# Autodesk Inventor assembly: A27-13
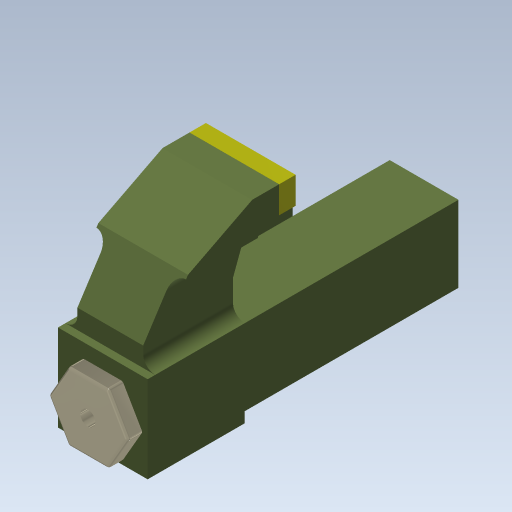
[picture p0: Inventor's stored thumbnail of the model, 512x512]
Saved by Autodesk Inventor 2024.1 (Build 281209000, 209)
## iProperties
Created: 2008-07
Part Number: A27-13
Document SubType Name: Assembly
Designer: y-shimohigashi
Stock Number: A24-13
Author: y-shimohigashi
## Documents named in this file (5)
- C:\Users\h-sato\Desktop\ブログ用モデル\Inventor\図面の作成\A27-13.iam
- C:\Users\h-sato\Desktop\R2024\Inventor2024基礎コース\練習問題\練習問題-27\P27-4締付板.ipt
- C:\Users\h-sato\Desktop\R2024\Inventor2024基礎コース\練習問題\練習問題-27\P27-6締付ネジ押え板.ipt
- C:\Users\h-sato\Desktop\R2024\Inventor2024基礎コース\練習問題\練習問題-27\P27-3締付金具.ipt
- C:\Users\h-sato\Desktop\R2024\Inventor2024基礎コース\練習問題\練習問題-27\P27-11ボルト.ipt
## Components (5 placed, 4 different names)
1. P27-4締付板:1 — 挿入:3, 挿入:4
2. P27-6締付ネジ押え板:1
3. P27-3締付金具:1
4. P27-11ボルト:1 — 挿入:4
5. P27-11ボルト:2 — 挿入:3
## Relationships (2: Insert 2)
- 挿入:3 [Insert]: P27-4締付板:1 ↔ P27-11ボルト:2
- 挿入:4 [Insert]: P27-4締付板:1 ↔ P27-11ボルト:1
